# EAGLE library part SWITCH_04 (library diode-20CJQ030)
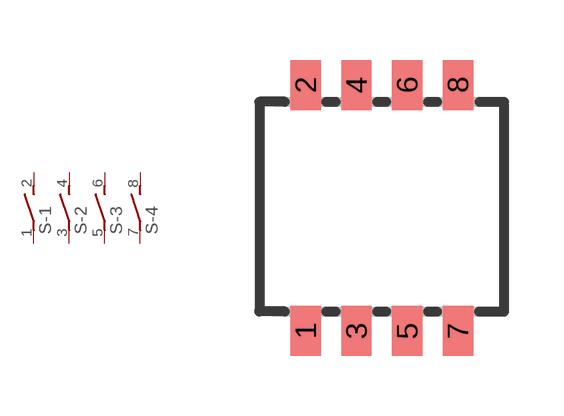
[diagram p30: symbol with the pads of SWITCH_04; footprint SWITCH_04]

Designator prefix S; gates -1=SWITCH_1 -2=SWITCH_1 -3=SWITCH_1 -4=SWITCH_1

## SWITCH_04  [SWITCH_04]
1  -1:1  pas
2  -1:2  pas
3  -2:1  pas
4  -2:2  pas
5  -3:1  pas
6  -3:2  pas
7  -4:1  pas
8  -4:2  pas

## Footprint SWITCH_04 (pad centres in mm)
www.e-switch.com (distributed by www.utech.ca) KAN series 1.27mm pitch (aka half pitch) SMT dip switches in 2,4,6,8,10 position packages
smd 0.76 x 1.25: 1 -1.9,-3.12; 2 -1.9,3.04; 3 -0.63,-3.12; 4 -0.63,3.04; 5 0.64,-3.12; 6 0.64,3.04; 7 1.91,-3.12; 8 1.91,3.04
